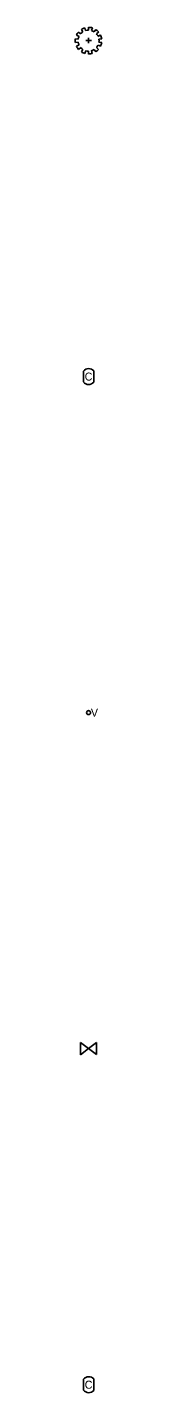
# Model space of a CAD drawing. Extents: x 98 to 2902, y -6 to 903.
# Drawn here: x 2698 to 2702, y 248.8 to 452 of the extents above; entities that cross this region are included whole.
import ezdxf

# ---------------------------------------------------------------- set-up
doc = ezdxf.new("R2010")
doc.units = 0
for name, color, linetype in [('V-COMM-EQPM', 7, 'Continuous'), ('V-SITE-VEGE', 7, 'Continuous'), ('V-UTIL-DEVC', 7, 'Continuous'), ('V-UTIL-VALT', 7, 'Continuous')]:
    doc.layers.add(name, color=color, linetype=linetype)

msp = doc.modelspace()

# ---------------------------------------------------------------- linework, layer by layer
at = {"layer": 'V-COMM-EQPM'}
for points in [[(2699.23, 400.81), (2699.23, 399.19)], [(2700.77, 399.15), (2700.77, 400.85)], [(2699.23, 250.81), (2699.23, 249.19)], [(2700.77, 249.15), (2700.77, 250.85)]]:
    msp.add_lwpolyline(points, dxfattribs=at)
for centre, start, end in [((2700.02, 400.19), 41.5928, 141.618), ((2700.02, 399.81), 218.382, 318.4072), ((2700.02, 250.19), 41.5928, 141.618), ((2700.02, 249.81), 218.382, 318.4072)]:
    msp.add_arc(centre, 1, start, end, dxfattribs=at)
at = {"layer": 'V-SITE-VEGE'}
for p, q in [((2698.49, 451.26), (2698.81, 450.98)), ((2699.17, 451.3), (2698.93, 451.65)), ((2699.46, 451.89), (2699.56, 451.47)), ((2700, 451.53), (2700.01, 451.96)), ((2700.57, 451.88), (2700.45, 451.47)), ((2700.84, 451.29), (2701.08, 451.64)), ((2701.51, 451.27), (2701.19, 450.99)), ((2698.03, 450.25), (2698.46, 450.18)), ((2698.46, 449.76), (2698.04, 449.69)), ((2698.58, 450.61), (2698.19, 450.78)), ((2698.19, 449.16), (2698.58, 449.35)), ((2699.58, 450), (2700.42, 450)), ((2700, 450.42), (2700, 449.58)), ((2701.81, 449.15), (2701.41, 449.31)), ((2701.42, 450.62), (2701.8, 450.82)), ((2701.97, 450.25), (2701.54, 450.19)), ((2701.54, 449.75), (2701.97, 449.7)), ((2698.83, 448.96), (2698.5, 448.68)), ((2698.94, 448.3), (2699.15, 448.68)), ((2699.58, 448.48), (2699.46, 448.07)), ((2700, 447.99), (2700, 448.42)), ((2700.43, 448.49), (2700.56, 448.08)), ((2701.08, 448.31), (2700.85, 448.68)), ((2701.17, 448.95), (2701.5, 448.68))]:
    msp.add_line(p, q, dxfattribs=at)
for radius, start, end in [(1.98, 139.7777, 156.0738), (1.56, 122.254, 140.086), (1.98, 105.972, 122.5562), (1.56, 89.9461, 106.3473), (1.98, 73.2952, 89.5718), (1.56, 57.451, 73.0843), (1.98, 40.7122, 57.1166), (1.98, 172.27, 188.583), (1.98, 204.5394, 220.9852), (1.56, 156.0557, 172.7558), (1.56, 188.0619, 204.0332), (1.56, 318.6432, 334.5795), (1.56, 24.4529, 40.4774), (1.56, 351.5431, 7.6203), (1.98, 7.9671, 24.8625), (1.98, 335.3123, 351.7042), (1.56, 221.2062, 236.7795), (1.98, 237.6108, 254.1981), (1.56, 254.31, 270.043), (1.98, 270.0356, 286.342), (1.56, 285.9559, 303.0564), (1.98, 302.8434, 319.0222)]:
    msp.add_arc((2700, 449.98), radius, start, end, dxfattribs=at)
at = {"layer": 'V-UTIL-DEVC'}
msp.add_circle((2700, 350), 0.298, dxfattribs=at)
at = {"layer": 'V-UTIL-VALT'}
for p, q in [((2700, 300), (2698.81, 300.9)), ((2698.81, 300.9), (2698.81, 299.1)), ((2701.19, 300.89), (2700, 300)), ((2701.19, 299.11), (2701.19, 300.89)), ((2698.81, 299.1), (2700, 300)), ((2700, 300), (2701.19, 299.11))]:
    msp.add_line(p, q, dxfattribs=at)

# ---------------------------------------------------------------- texts
at = {"layer": 'V-COMM-EQPM'}
for p in [(2699.43, 399.4), (2699.43, 249.4)]:
    msp.add_text('C', height=1.19, dxfattribs=at).set_placement(p)
at = {"layer": 'V-UTIL-DEVC'}
msp.add_text('V', height=1.19, dxfattribs=at).set_placement((2700.35, 349.4))

doc.saveas('drawing.dxf')
